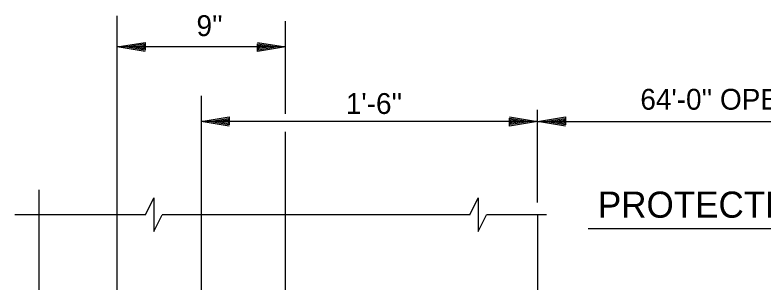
# Model space of a CAD drawing. Extents: x 18232 to 22378, y 12454 to 22381.
# Drawn here: x 22369.908 to 22373.245, y 22379.546 to 22380.74 of the extents above; entities that cross this region are included whole.
import ezdxf

# ---------------------------------------------------------------- set-up
doc = ezdxf.new("R2010")
doc.units = 0
for name, color, linetype in [('Level 1', 7, 'Continuous'), ('Level 2', 7, 'Continuous'), ('Level 3', 7, 'Continuous'), ('Level 50', 7, 'Continuous')]:
    doc.layers.add(name, color=color, linetype=linetype)

msp = doc.modelspace()

# ---------------------------------------------------------------- linework, layer by layer
at = {"layer": 'Level 1'}
for points in [[(22370.4894, 22379.8466), (22370.5266, 22379.9216), (22370.5266, 22379.7718), (22370.5641, 22379.8466)], [(22371.9366, 22379.8466), (22371.9739, 22379.9216), (22371.9739, 22379.7718), (22372.0114, 22379.8466)]]:
    msp.add_lwpolyline(points, dxfattribs=at)
at = {"layer": 'Level 2'}
for p, q in [((22371.1139, 22380.5966), (22370.3639, 22380.5966)), ((22372.2389, 22380.2633), (22370.7389, 22380.2633)), ((22370.0151, 22379.4395), (22370.0151, 22379.9573)), ((22370.4894, 22379.8466), (22369.9075, 22379.8466)), ((22371.9366, 22379.8466), (22370.5641, 22379.8466)), ((22372.2795, 22379.8466), (22372.0114, 22379.8466))]:
    msp.add_line(p, q, dxfattribs=at)
at = {"layer": 'Level 3'}
for p, q in [((22370.3639, 22379.0693), (22370.3639, 22380.7365)), ((22371.1139, 22380.2983), (22371.1139, 22380.7126)), ((22370.3639, 22380.5966), (22370.3639, 22380.5966)), ((22370.3985, 22380.5966), (22370.3985, 22380.5966)), ((22371.0792, 22380.5966), (22371.0792, 22380.5966)), ((22371.1139, 22380.5966), (22371.1139, 22380.5966)), ((22370.7389, 22380.3786), (22370.7389, 22377.2829)), ((22372.2389, 22379.9008), (22372.2389, 22380.3159)), ((22372.2043, 22380.2633), (22372.2043, 22380.2633)), ((22372.2389, 22380.2633), (22373.8058, 22380.2633)), ((22372.2389, 22380.2633), (22372.2389, 22380.2633)), ((22372.2389, 22380.2633), (22372.2389, 22380.2633)), ((22372.2736, 22380.2633), (22372.2736, 22380.2633)), ((22371.1139, 22379.0802), (22371.1139, 22380.2167)), ((22372.2389, 22379.8466), (22372.2389, 22378.9691)), ((22372.4641, 22379.7855), (22373.986, 22379.7855))]:
    msp.add_line(p, q, dxfattribs=at)
for points in [[(22370.4885, 22380.5759), (22370.3639, 22380.5966), (22370.4885, 22380.6173), (22370.4885, 22380.5819), (22370.3985, 22380.5966), (22370.4832, 22380.6106), (22370.4832, 22380.5879), (22370.4319, 22380.5966), (22370.4779, 22380.6039), (22370.4779, 22380.5946), (22370.4665, 22380.5966)], [(22370.9892, 22380.6173), (22371.1139, 22380.5966), (22370.9892, 22380.5759), (22370.9892, 22380.6113), (22371.0792, 22380.5966), (22370.9945, 22380.5826), (22370.9945, 22380.6053), (22371.0459, 22380.5966), (22370.9999, 22380.5893), (22370.9999, 22380.5986), (22371.0112, 22380.5966)], [(22372.1143, 22380.2839), (22372.2389, 22380.2633), (22372.1143, 22380.2426), (22372.1143, 22380.2779), (22372.2043, 22380.2633), (22372.1196, 22380.2493), (22372.1196, 22380.2719), (22372.1709, 22380.2633), (22372.1249, 22380.2559), (22372.1249, 22380.2653), (22372.1363, 22380.2633)], [(22372.3636, 22380.2426), (22372.2389, 22380.2633), (22372.3636, 22380.2839), (22372.3636, 22380.2486), (22372.2736, 22380.2633), (22372.3583, 22380.2773), (22372.3583, 22380.2546), (22372.3069, 22380.2633), (22372.3529, 22380.2706), (22372.3529, 22380.2613), (22372.3416, 22380.2633)]]:
    msp.add_lwpolyline(points, dxfattribs=at)
at = {"layer": 'Level 50'}
for p, q in [((22370.7389, 22380.2633), (22370.7389, 22380.2633)), ((22370.7735, 22380.2633), (22370.7735, 22380.2633))]:
    msp.add_line(p, q, dxfattribs=at)
msp.add_lwpolyline([(22370.8635, 22380.2426), (22370.7389, 22380.2633), (22370.8635, 22380.2839), (22370.8635, 22380.2486), (22370.7735, 22380.2633), (22370.8582, 22380.2773), (22370.8582, 22380.2546), (22370.8069, 22380.2633), (22370.8529, 22380.2706), (22370.8529, 22380.2613), (22370.8415, 22380.2633)], dxfattribs=at)

# ---------------------------------------------------------------- texts
at = {"layer": 'Level 3'}
for s, height, p in [("9''", 0.09317, (22370.7174, 22380.6453)), ("1'-6''", 0.09317, (22371.3836, 22380.2971)), ("64'-0'' OPENING", 0.093167, (22372.6976, 22380.3161)), ('PROTECTED SIDE', 0.116792, (22372.5082, 22379.8333))]:
    msp.add_text(s, height=height, dxfattribs=at).set_placement(p)

doc.saveas('drawing.dxf')
